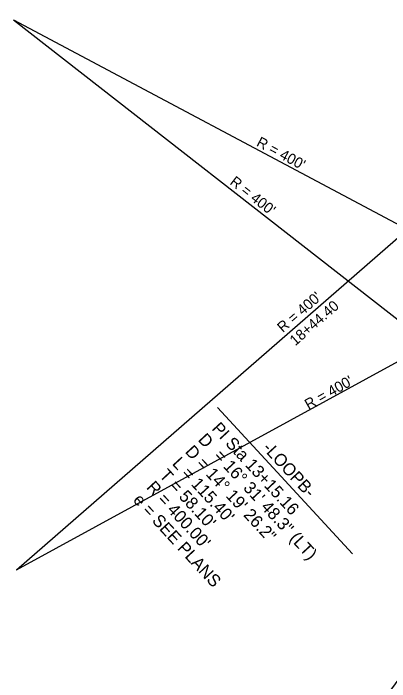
# Model space of a CAD drawing. Extents: x 1702862 to 1704514, y 793768 to 796215.
# Drawn here: x 1702910.1 to 1703124.4, y 795003.7 to 795384 of the extents above; entities that cross this region are included whole.
import ezdxf

# ---------------------------------------------------------------- set-up
doc = ezdxf.new("R2010")
doc.units = 0
for name, color, linetype in [('Prop Dimension', 7, 'Continuous'), ('Prop Dimension Text', 7, 'Continuous'), ('Prop Horizontal Alignment', 7, 'Continuous'), ('Prop Horizontal Alignment Curve and Spiral Data', 7, 'Continuous')]:
    doc.layers.add(name, color=color, linetype=linetype)

msp = doc.modelspace()

# ---------------------------------------------------------------- linework, layer by layer
at = {"layer": 'Prop Dimension'}
for p, q in [((1702910.07, 795380.31), (1703225.66, 795134.54)), ((1702910.07, 795380.31), (1703263.28, 795192.59)), ((1702911.8, 795067.36), (1703213.54, 795329.94)), ((1702911.8, 795067.36), (1703262.92, 795258.97))]:
    msp.add_line(p, q, dxfattribs=at)
at = {"layer": 'Prop Horizontal Alignment'}
for centre, radius, start, end in [((1703981.48, 795998.22), 1000, 201.8874, 222.70907), ((1703449.23, 794764.8), 400, 136.823, 153.353)]:
    msp.add_arc(centre, radius, start, end, dxfattribs=at)
at = {"layer": 'Prop Horizontal Alignment Curve and Spiral Data'}
msp.add_line((1703026.35, 795159.75), (1703103.28, 795076.41), dxfattribs=at)

# ---------------------------------------------------------------- texts
at = {"layer": 'Prop Dimension Text'}
for s, rotation, p in [("R = 400'", 331.7376, (1703048.05, 795308.82)), ("R = 400'", 321.9909, (1703032.94, 795287.11)), ("R = 400'", 41.0304, (1703063.58, 795202.01)), ('18+44.40', 41.0304, (1703070.69, 795194.52)), ("R = 400'", 29.4306, (1703078.15, 795158.33))]:
    msp.add_text(s, height=6, rotation=rotation, dxfattribs=at).set_placement(p)
at = {"layer": 'Prop Horizontal Alignment Curve and Spiral Data'}
for s, p in [('PI Sta 13+15.16', (1703022.67, 795147.39)), ('D', (1703014.86, 795141.11)), ('D = 14%%d 19\' 26.2"', (1703007.52, 795134.32)), ('-LOOPB-', (1703051.68, 795136.3)), ('= 16%%d 31\' 48.3" (LT)', (1703023.8, 795131.86)), ("L = 115.40'", (1703000.17, 795127.54)), ("T = 58.10'", (1702992.82, 795120.76)), ("R = 400.00'", (1702985.47, 795113.97)), ('e = SEE PLANS', (1702977.86, 795106.71))]:
    msp.add_text(s, height=7, rotation=312.7091, dxfattribs=at).set_placement(p)

doc.saveas('drawing.dxf')
